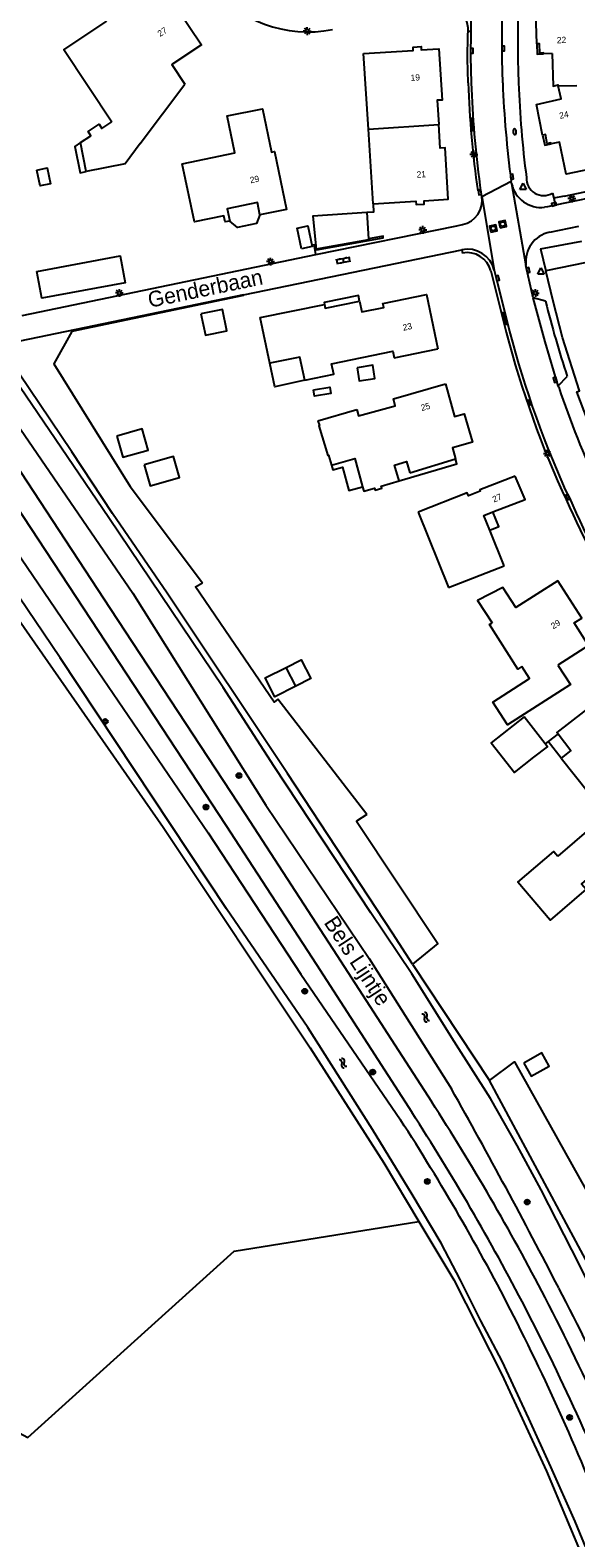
# Model space of a CAD drawing. Extents: x 126000 to 131009, y 393000 to 395500.
# Drawn here: x 130307.9 to 130394.9, y 394768.1 to 395008.4 of the extents above; entities that cross this region are included whole.
import ezdxf

# ---------------------------------------------------------------- set-up
doc = ezdxf.new("R2010")
doc.units = 0
for name, color, linetype in [('gg-afsc-erfafscheiding', 7, 'Continuous'), ('gg-afsc-hekwerk', 7, 'Continuous'), ('gg-afsc-muur', 7, 'Continuous'), ('gg-anno-huisnummerreeks BGT', 7, 'Continuous'), ('gg-anno-openbare ruimte label', 7, 'Continuous'), ('gg-bbg-bijgebouw', 7, 'Continuous'), ('gg-bbg-gedigitaliseerde bebouwing', 7, 'Continuous'), ('gg-bbg-gedigitaliseerde bijgebouw', 7, 'Continuous'), ('gg-bbg-hoofdgebouw', 7, 'Continuous'), ('gg-bbg-luifel en loopbrug', 7, 'Continuous'), ('gg-bbg-tussenscheiding', 7, 'Continuous'), ('gg-knt-verharding', 7, 'Continuous'), ('gg-knt-verharding nz', 7, 'Continuous'), ('gg-kntw-bovenkant insteek waterloop', 7, 'Continuous'), ('gt-grn-groengrens', 7, 'Continuous'), ('gt-grn-vlakafsluiter', 7, 'Continuous'), ('gt-grn-weggrens', 7, 'Continuous'), ('gt-symb-boom', 7, 'Continuous'), ('gt-symb-brandkraan', 7, 'Continuous'), ('gt-symb-klinker verharding', 7, 'Continuous'), ('gt-symb-kolk', 7, 'Continuous'), ('gt-symb-lichtmast', 7, 'Continuous'), ('gt-symb-rioolschacht', 7, 'Continuous'), ('gt-symb-tegel verharding', 7, 'Continuous'), ('gt-symb-waterafsluiter', 7, 'Continuous'), ('gt-symb-watersymbool', 7, 'Continuous')]:
    doc.layers.add(name, color=color, linetype=linetype)

# ---------------------------------------------------------------- blocks, each defined once
blk = doc.blocks.new('gt0-KOLK')
at = {"layer": 'gt-symb-kolk'}
blk.add_lwpolyline([(0, 0), (0.38, 0), (0.38, 0.4), (-0.37, 0.4), (-0.37, 0), (0, 0)], dxfattribs=at)
blk = doc.blocks.new('gt0-LMAST')
at = {"layer": 'gt-symb-lichtmast'}
for p, q in [((-0.18, 0.17), (-0.45, 0.44)), ((0, 0.25), (0, 0.62)), ((0.17, 0.17), (0.44, 0.44)), ((-0.25, 0), (-0.63, 0)), ((-0.18, -0.18), (-0.45, -0.45)), ((0, -0.25), (0, -0.63)), ((0.44, -0.45), (0.17, -0.18)), ((0.25, 0), (0.62, 0))]:
    blk.add_line(p, q, dxfattribs=at)
blk.add_circle((0, 0), 0.25, dxfattribs=at)
blk = doc.blocks.new('gt0-BR')
at = {"layer": 'gt-symb-brandkraan'}
for centre, radius, start, end in [((-0.24, 0), 0.206, 107.5669, 252.4331), ((0.6, -2.66), 3, 106.892, 107.5669), ((0, -0.69), 0.938, 73.108, 106.892), ((-0.6, -2.66), 3, 72.4331, 73.108), ((0.24, 0), 0.206, 287.567, 72.4331), ((0.6, 2.66), 3, 252.4331, 253.108), ((0, 0.69), 0.938, 253.108, 286.8921), ((-0.6, 2.66), 3, 286.8921, 287.567)]:
    blk.add_arc(centre, radius, start, end, dxfattribs=at)
blk = doc.blocks.new('gt0-WAFSL')
at = {"layer": 'gt-symb-waterafsluiter'}
for p, q in [((-0.5, -0.33), (0, 0.67)), ((0, 0.67), (0.5, -0.33)), ((0.5, -0.33), (-0.5, -0.33))]:
    blk.add_line(p, q, dxfattribs=at)
blk = doc.blocks.new('gt0-TEG1')
at = {"layer": 'gt-symb-tegel verharding'}
for p, q in [((-1.12, 0), (1.12, 0)), ((-0.9, -0.25), (-0.9, 0.25)), ((-0.45, -0.25), (-0.45, 0.25)), ((0, -0.25), (0, 0.25)), ((0.45, -0.25), (0.45, 0.25)), ((0.9, -0.25), (0.9, 0.25))]:
    blk.add_line(p, q, dxfattribs=at)
blk = doc.blocks.new('gt0-RS')
at = {"layer": 'gt-symb-rioolschacht'}
blk.add_lwpolyline([(-0.5, -0.5), (0.5, -0.5), (0.5, 0.5), (-0.5, 0.5)], close=True, dxfattribs=at)
blk.add_circle((0, 0), 0.375, dxfattribs=at)
blk = doc.blocks.new('gt0-BOOM')
at = {"layer": 'gt-symb-boom'}
for radius in [0.4, 0.2]:
    blk.add_circle((0, 0), radius, dxfattribs=at)
blk = doc.blocks.new('gt0-WA')
at = {"layer": 'gt-symb-watersymbool'}
for centre, start, end in [((-0.32, 0.02), 28.0725, 151.9275), ((0.43, 0.42), 208.0725, 331.9275), ((-0.32, -0.43), 28.0725, 151.9275), ((0.43, -0.03), 208.0725, 331.9275)]:
    blk.add_arc(centre, 0.425, start, end, dxfattribs=at)
blk = doc.blocks.new('gt0-KL1')
at = {"layer": 'gt-symb-klinker verharding'}
for p, q in [((-1.15, 0.3), (1.15, 0.3)), ((-1, -0.3), (-1, 0.3)), ((-0.5, 0.3), (-0.5, 0.45)), ((0, -0.3), (0, 0.3)), ((0.5, 0.3), (0.5, 0.45)), ((1, -0.3), (1, 0.3)), ((-1.15, -0.3), (1.15, -0.3)), ((-0.5, -0.45), (-0.5, -0.3)), ((0.5, -0.45), (0.5, -0.3))]:
    blk.add_line(p, q, dxfattribs=at)

msp = doc.modelspace()

# ---------------------------------------------------------------- linework, layer by layer
at = {"layer": 'gg-afsc-erfafscheiding'}
for p, q in [((130353.44, 394972.64), (130353.16, 394974.31)), ((130306.66, 394962.91), (130353.44, 394972.64))]:
    msp.add_line(p, q, dxfattribs=at)
for points in [[(130362.57, 394980.73), (130362.65, 394979.38), (130361.56, 394979.31)], [(130341.94, 394966.09), (130314.56, 394960.37), (130311.72, 394955.21), (130323.87, 394935.67), (130335.39, 394920.32)]]:
    msp.add_lwpolyline(points, dxfattribs=at)
at = {"layer": 'gg-afsc-hekwerk'}
msp.add_line((130368.85, 394859.54), (130381.11, 394841.01), dxfattribs=at)
for points in [[(130347.4, 394901.79), (130346.82, 394901.29), (130334.27, 394919.66), (130335.39, 394920.32)], [(130361.56, 394883.4), (130359.89, 394882.32), (130372.89, 394862.84), (130368.85, 394859.54)], [(130381.11, 394841.01), (130385.07, 394843.99), (130396.51, 394823.51), (130409.61, 394799.92)]]:
    msp.add_lwpolyline(points, dxfattribs=at)
at = {"layer": 'gg-afsc-muur'}
msp.add_line((130390.43, 394895.01), (130389.96, 394894.65), dxfattribs=at)
msp.add_lwpolyline([(130353.5, 394973.48), (130353.52, 394973.36), (130364.18, 394975.31), (130364.14, 394975.55), (130361.84, 394975.12)], dxfattribs=at)
at = {"layer": 'gg-bbg-bijgebouw'}
for p, q in [((130361.56, 394979.31), (130361.84, 394975.12)), ((130353.5, 394973.48), (130353.47, 394973.47)), ((130389.96, 394894.65), (130386.6, 394898.95))]:
    msp.add_line(p, q, dxfattribs=at)
msp.add_lwpolyline([(130361.84, 394975.12), (130361.84, 394974.99), (130353.5, 394973.48)], dxfattribs=at)
at = {"layer": 'gg-bbg-gedigitaliseerde bebouwing'}
for p, q in [((130361.81, 394992.62), (130361.04, 395004.65)), ((130325.47, 394990.31), (130332.59, 394999.8)), ((130362.57, 394980.73), (130361.81, 394992.62)), ((130316.87, 394985.88), (130315.94, 394990.47)), ((130346.13, 394955.3), (130344.56, 394962.59)), ((130365.9, 394956.16), (130372.87, 394957.6)), ((130353.78, 394946.14), (130359.96, 394947.94)), ((130368.42, 394937.87), (130375.69, 394940.07)), ((130369.72, 394931.6), (130374.55, 394919.56)), ((130374.55, 394919.56), (130383.44, 394923.02)), ((130403.79, 394886.91), (130391.98, 394876.78))]:
    msp.add_line(p, q, dxfattribs=at)
for points in [[(130320.09, 395009.83), (130313.3, 395005.33), (130320.95, 394993.8)], [(130315.94, 394990.47), (130317.61, 394991.58), (130317.17, 394992.24), (130318.92, 394993.41), (130319.36, 394992.74), (130320.95, 394993.8)], [(130325.47, 394990.31), (130323.07, 394987.11), (130316.87, 394985.88)], [(130351.68, 394952.59), (130356.28, 394953.55), (130355.93, 394955.21), (130365.68, 394957.24), (130365.9, 394956.16)], [(130351.68, 394952.59), (130350.91, 394956.3), (130346.13, 394955.3)], [(130359.96, 394947.94), (130360.25, 394946.92), (130366.09, 394948.55), (130365.79, 394949.64), (130374.07, 394952.05)], [(130353.78, 394946.14), (130354.02, 394945.37), (130353.91, 394945.34), (130355.36, 394940.61), (130355.47, 394940.64), (130355.94, 394939.09)], [(130355.94, 394939.09), (130359.63, 394940.12), (130360.89, 394935.63)], [(130366.71, 394936.56), (130365.97, 394939.07), (130367.9, 394939.64), (130368.42, 394937.87)], [(130360.89, 394935.63), (130361.09, 394934.91), (130362.8, 394935.41), (130362.89, 394935.09), (130363.97, 394935.41), (130363.87, 394935.72), (130366.71, 394936.56)], [(130392, 394920.63), (130385.32, 394916.36), (130383.25, 394919.57), (130379.2, 394917.52), (130381.51, 394913.92)], [(130386.27, 394906.97), (130385.62, 394906.55), (130381.08, 394913.65), (130381.51, 394913.92)], [(130392.01, 394907.21), (130394, 394904.1), (130383.97, 394897.69), (130381.65, 394901.32), (130387.5, 394905.05), (130386.27, 394906.97)], [(130392.02, 394896.24), (130394.05, 394893.61), (130392.51, 394892.39)], [(130392.51, 394892.39), (130396.85, 394886.92), (130408.44, 394896.11)], [(130399.53, 394875.58), (130395.78, 394872.33), (130396.49, 394871.5), (130390.75, 394866.58), (130385.6, 394872.6), (130391.34, 394877.51), (130391.98, 394876.78)]]:
    msp.add_lwpolyline(points, dxfattribs=at)
at = {"layer": 'gg-bbg-gedigitaliseerde bijgebouw'}
msp.add_line((130350.24, 394903.86), (130348.73, 394906.85), dxfattribs=at)
for points in [[(130309, 394986.09), (130310.64, 394986.43), (130311.17, 394983.93), (130309.53, 394983.58), (130309, 394986.09)], [(130361.56, 394979.31), (130352.96, 394978.74), (130353.47, 394973.47)], [(130308.97, 394969.95), (130322.28, 394972.44), (130323.08, 394968.15), (130309.77, 394965.66), (130308.97, 394969.95)], [(130360.03, 394954.59), (130360.36, 394952.49), (130362.85, 394952.88), (130362.52, 394954.98), (130360.03, 394954.59)], [(130321.71, 394943.68), (130322.67, 394940.32), (130326.71, 394941.48), (130325.75, 394944.84), (130321.71, 394943.68)], [(130326.09, 394939.11), (130327.05, 394935.78), (130331.72, 394937.11), (130330.76, 394940.45), (130326.09, 394939.11)], [(130348.73, 394906.85), (130351.12, 394908.05), (130352.62, 394905.06), (130350.24, 394903.86)], [(130386.6, 394898.95), (130381.38, 394894.84), (130385.07, 394890.11), (130388.19, 394892.54)], [(130386.57, 394843.79), (130387.74, 394841.69), (130390.62, 394843.3), (130389.45, 394845.4), (130386.57, 394843.79)]]:
    msp.add_lwpolyline(points, dxfattribs=at)
at = {"layer": 'gg-bbg-hoofdgebouw'}
for p, q in [((130391.06, 395004.65), (130389.73, 395004.6)), ((130344.56, 394962.59), (130354.81, 394964.7)), ((130383.44, 394923.02), (130381.15, 394928.72)), ((130396.9, 394910.33), (130392.01, 394907.21))]:
    msp.add_line(p, q, dxfattribs=at)
for points in [[(130329.45, 395014.7), (130335.2, 395006.05), (130330.51, 395002.93), (130332.59, 394999.8)], [(130388.63, 395006.22), (130388.46, 395011.18), (130392, 395011.31), (130391.9, 395014.36)], [(130361.04, 395004.65), (130368.94, 395005.15), (130368.92, 395005.7), (130370.22, 395005.81), (130370.24, 395005.25), (130373.04, 395005.42), (130373.54, 394997.25), (130372.78, 394997.23), (130373.01, 394993.34)], [(130389.73, 395004.6), (130389.72, 395004.76), (130389.11, 395004.74), (130389.06, 395006.24), (130388.63, 395006.22)], [(130391.06, 395004.65), (130391.25, 394999.49), (130392.01, 394999.66), (130392.04, 394999.51)], [(130389.57, 394991.67), (130388.57, 394996.53), (130392.52, 394997.45), (130392.04, 394999.51)], [(130332.15, 394987.09), (130340.52, 394988.87), (130339.31, 394994.73), (130344.94, 394995.88), (130346.36, 394988.97), (130346.87, 394989.08), (130348.76, 394979.83), (130344.53, 394978.96)], [(130362.57, 394980.73), (130369.37, 394981.14), (130369.4, 394980.59), (130370.72, 394980.67), (130370.69, 394981.22), (130374.51, 394981.46), (130374.02, 394989.62), (130373.25, 394989.57), (130373.01, 394993.34)], [(130390.92, 394990.27), (130390.89, 394990.42), (130390.3, 394990.3), (130390, 394991.76), (130389.57, 394991.67)], [(130401.22, 394987.09), (130393.32, 394985.45), (130392.24, 394990.55), (130390.92, 394990.27)], [(130339.73, 394977.98), (130338.99, 394977.83), (130338.8, 394978.78), (130334.12, 394977.83), (130332.15, 394987.09)], [(130344.53, 394978.96), (130344.13, 394980.92), (130339.32, 394979.94), (130339.73, 394977.98)], [(130360.4, 394965.2), (130360.75, 394963.49), (130364.25, 394964.19), (130364.12, 394964.83), (130371.06, 394966.26), (130372.87, 394957.6)], [(130354.81, 394964.7), (130354.93, 394964.07), (130360.4, 394965.2)], [(130374.07, 394952.05), (130375.53, 394946.82), (130377.09, 394947.25), (130378.39, 394942.75), (130375.19, 394941.85), (130375.69, 394940.07)], [(130385.21, 394937.33), (130379.56, 394935.13), (130379.64, 394934.93), (130377.76, 394934.16), (130377.56, 394934.65), (130369.72, 394931.6)], [(130381.64, 394931.61), (130386.79, 394933.59), (130385.21, 394937.33)], [(130381.15, 394928.72), (130380.21, 394931.06), (130381.64, 394931.61)], [(130396.9, 394910.33), (130394.61, 394913.92), (130395.79, 394914.68), (130392, 394920.63)], [(130401.98, 394904.32), (130391.83, 394896.47), (130392.02, 394896.24)]]:
    msp.add_lwpolyline(points, dxfattribs=at)
at = {"layer": 'gg-bbg-luifel en loopbrug'}
for p in [(130392.02, 394896.24), (130392.51, 394892.39)]:
    msp.add_line(p, (130390.43, 394895.01), dxfattribs=at)
for points in [[(130388.63, 395006.22), (130388.69, 395004.56), (130389.73, 395004.6)], [(130315.94, 394990.47), (130315.05, 394989.88), (130315.9, 394985.68), (130316.87, 394985.88)], [(130389.57, 394991.67), (130389.9, 394990.06), (130390.92, 394990.27)], [(130344.53, 394978.96), (130343.96, 394977.59), (130340.97, 394976.97), (130339.73, 394977.98)], [(130351.13, 394973.57), (130350.46, 394976.85), (130352.17, 394977.2), (130352.84, 394973.92), (130351.13, 394973.57)], [(130335.13, 394963.18), (130335.84, 394959.76), (130339.25, 394960.47), (130338.55, 394963.88), (130335.13, 394963.18)], [(130360.4, 394965.2), (130360.22, 394966.1), (130354.75, 394965), (130354.81, 394964.7)], [(130351.68, 394952.59), (130346.93, 394951.57), (130346.13, 394955.3)], [(130353.04, 394951.1), (130355.66, 394951.51), (130355.82, 394950.49), (130353.2, 394950.08), (130353.04, 394951.1)], [(130366.71, 394936.56), (130375.92, 394939.28), (130375.69, 394940.07)], [(130355.94, 394939.09), (130356.15, 394938.32), (130357.67, 394938.75), (130358.71, 394935.02), (130360.89, 394935.63)], [(130381.15, 394928.72), (130382.57, 394929.29), (130381.64, 394931.61)], [(130350.24, 394903.86), (130346.88, 394902.17), (130345.37, 394905.16), (130348.73, 394906.85)]]:
    msp.add_lwpolyline(points, dxfattribs=at)
at = {"layer": 'gg-bbg-tussenscheiding'}
for p, q in [((130392.04, 394999.51), (130395.04, 394999.6)), ((130361.81, 394992.62), (130373.01, 394993.34))]:
    msp.add_line(p, q, dxfattribs=at)
msp.add_lwpolyline([(130388.19, 394892.54), (130390.32, 394894.18), (130389.96, 394894.65)], dxfattribs=at)
at = {"layer": 'gg-knt-verharding'}
for p, q in [((130377.68, 395008.25), (130378.13, 395008.24)), ((130415.63, 394985.47), (130391.56, 394980.49)), ((130392.98, 394981.95), (130415.38, 394986.63)), ((130379.71, 394982.84), (130379.59, 394983.71)), ((130384.62, 394983.96), (130384.56, 394984.31)), ((130379.24, 394982.77), (130379.71, 394982.84)), ((130391.13, 394982.43), (130391.33, 394981.62)), ((130392.98, 394981.95), (130391.33, 394981.62)), ((130353.44, 394972.64), (130375.91, 394977.23)), ((130375.91, 394977.23), (130376.81, 394977.42)), ((130390.71, 394976.21), (130395.32, 394977.18)), ((130341.92, 394966.2), (130376.7, 394973.4)), ((130376.7, 394973.4), (130376.81, 394972.86)), ((130389.24, 394973.52), (130395.82, 394974.79)), ((130389.24, 394973.52), (130390.07, 394970.04)), ((130381.32, 394970.02), (130383.33, 394961.99)), ((130381.86, 394970.16), (130382.07, 394969.29)), ((130382.07, 394969.29), (130383.86, 394962.12)), ((130390.04, 394965.18), (130388.06, 394965.71)), ((130392.06, 394951.73), (130393.5, 394953.19)), ((130392.13, 394951.48), (130392.06, 394951.73)), ((130392.68, 394934.92), (130393.33, 394933.61)), ((130393.18, 394935.14), (130393.83, 394933.84))]:
    msp.add_line(p, q, dxfattribs=at)
for points in [[(130377.71, 395000), (130377.62, 395003.83), (130377.64, 395007.67), (130377.68, 395008.25)], [(130378.13, 395008.24), (130378.1, 395004.12), (130378.19, 395000)], [(130379.88, 394981.9), (130379.88, 394981.9), (130379.71, 394982.84)], [(130391.56, 394980.49), (130390.33, 394980.23), (130389.88, 394980.16)], [(130388.06, 394965.71), (130386.99, 394970.41), (130386.9, 394970.88)], [(130400.84, 394936.26), (130397.78, 394943.46), (130395.02, 394950.78), (130395.42, 394950.91), (130392.75, 394959.41), (130391.22, 394965.21), (130390.07, 394970.04)], [(130341.92, 394966.2), (130303.2, 394958.17), (130303.05, 394958.86)], [(130291.2, 394954.58), (130317.59, 394914.47), (130339.1, 394881.69), (130353.55, 394859.51), (130368.71, 394835.95)], [(130295.17, 394955.17), (130296.17, 394953.51), (130320.69, 394916.21), (130342.22, 394883.38), (130356.8, 394860.99), (130371.86, 394837.65)]]:
    msp.add_lwpolyline(points, dxfattribs=at)
for centre, radius, start, end in [((130550.55, 395006.52), 167.48, 172.0808, 182.2328), ((130551.86, 395006.24), 166.26, 172.0045, 182.1512), ((130553.09, 395006.39), 174.98, 175.227, 179.394), ((130352.24, 395028.4), 20.29, 218.6521, 280.986), ((130374.38, 395008.58), 3.32, 354.283, 65.702), ((130534.6, 395005.27), 156.98, 181.9255, 188.2426), ((130535.08, 395005.26), 156.98, 181.9205, 187.8903), ((130550.59, 395006.53), 167.51, 182.2348, 187.6231), ((130551.46, 395006.22), 165.85, 182.1485, 187.3845), ((130389.35, 394984.97), 4.83, 192.0154, 276.3674), ((130389.72, 394984.78), 2.74, 177.4339, 301.0781), ((130376.02, 394981.25), 3.91, 281.7077, 9.5719), ((130391.71, 394971.48), 4.84, 101.8542, 187.044), ((130377.59, 394969.09), 4.4, 13.9987, 101.6735), ((130377.59, 394969.09), 3.85, 14.0059, 101.6734), ((130536.26, 395000.93), 150.53, 193.7386, 198.4914), ((130540.78, 395001.24), 162.28, 193.9971, 204.1228), ((130540.72, 395001.21), 161.66, 193.9946, 204.1245), ((130537.73, 395000.2), 153.53, 198.5028, 204.9395), ((130541.7, 394998.6), 161.99, 203.6527, 218.7213), ((130541.76, 394998.64), 161.5, 203.6556, 218.7189), ((130049.56, 394629.92), 383.44, 27.4096, 32.8034), ((130052.31, 394631.55), 376.69, 27.3753, 32.8629), ((130049.54, 394629.94), 383.45, 20.978, 27.4057), ((130052.12, 394631.42), 376.92, 21.3087, 27.3799)]:
    msp.add_arc(centre, radius, start, end, dxfattribs=at)
at = {"layer": 'gg-knt-verharding nz'}
msp.add_lwpolyline([(130392.06, 394951.73), (130389.97, 394958.7), (130388.06, 394965.71)], dxfattribs=at)
at = {"layer": 'gg-kntw-bovenkant insteek waterloop'}
for points in [[(130414.31, 394771.26), (130410.08, 394780.34), (130406.92, 394787.68), (130400.34, 394801.91), (130394.22, 394814), (130389.33, 394823.58), (130385.5, 394830.66), (130381.27, 394838.14), (130375.45, 394847.24), (130368.73, 394858.02), (130362.18, 394867.72), (130346.79, 394891.05), (130338.65, 394903.66), (130320.47, 394930.69), (130305.36, 394952.89), (130303.67, 394955.23), (130301.53, 394954.42), (130301.07, 394954)], [(130301.07, 394954), (130301.04, 394952.55), (130324.28, 394918.68), (130345.47, 394884.9), (130361.93, 394860.45), (130375.04, 394839.66)], [(130284.95, 394950.01), (130286.14, 394950.89), (130288, 394951.36), (130314.8, 394912.03), (130336.26, 394880.49), (130351.07, 394857.95), (130366.91, 394834.75)], [(130427.63, 394665.15), (130426.05, 394670.47), (130423.14, 394683.22), (130419.53, 394697.87), (130416.49, 394708.15), (130413.34, 394719.45), (130410.33, 394729.27), (130407.67, 394737.45), (130404.96, 394745.02), (130401.89, 394752.73), (130398.65, 394761.31), (130394.73, 394770.7), (130390.87, 394779.42), (130387.39, 394787.13), (130383.11, 394796.26), (130379.7, 394802.73), (130376.5, 394809.2), (130373.41, 394815.06), (130368.8, 394822.84), (130362.49, 394833.17), (130352.17, 394849.44), (130339.18, 394868.34), (130312.69, 394908.34), (130298.27, 394929.68)]]:
    msp.add_lwpolyline(points, dxfattribs=at)
for centre, radius, start, end in [((129502.61, 394349.03), 1000.93, 27.28926, 29.35231), ((130074.2, 394644.95), 348.86, 27.0238, 32.9608), ((129502.49, 394348.89), 1001.1, 24.95233, 27.29306), ((130074.16, 394644.95), 348.89, 20.2997, 27.0208)]:
    msp.add_arc(centre, radius, start, end, dxfattribs=at)
at = {"layer": 'gt-grn-groengrens'}
for p, q in [((130396.54, 394971.38), (130390.07, 394970.04)), ((130361.56, 394883.4), (130347.4, 394901.79))]:
    msp.add_line(p, q, dxfattribs=at)
for points in [[(130368.85, 394859.54), (130365.67, 394864.51), (130358.01, 394876.13), (130348.95, 394889.93), (130329.76, 394918.66), (130321.07, 394931.37), (130314.55, 394941.18), (130302.65, 394958.78)], [(130282.69, 394947.97), (130329.1, 394881.36), (130352.55, 394846.19), (130364.27, 394827.87), (130369.85, 394818.55)], [(130405.52, 394794.77), (130401.74, 394802.56), (130381.11, 394841.01)], [(130236.28, 394788.4), (130281.06, 394798.36), (130307.57, 394784.11), (130340.41, 394813.8), (130369.85, 394818.55)], [(130369.85, 394818.55), (130375.42, 394809.23), (130383.08, 394794.16), (130390.16, 394778.77), (130405.31, 394742.62), (130417.03, 394703.05), (130424.16, 394671.74), (130425.35, 394665.9)]]:
    msp.add_lwpolyline(points, dxfattribs=at)
at = {"layer": 'gt-grn-vlakafsluiter'}
msp.add_line((130341.94, 394966.09), (130341.92, 394966.2), dxfattribs=at)
at = {"layer": 'gt-grn-weggrens'}
for p, q in [((130379.88, 394981.9), (130384.56, 394984.31)), ((130384.62, 394983.96), (130386.9, 394970.88)), ((130379.88, 394981.9), (130381.86, 394970.16)), ((130391.33, 394981.62), (130391.56, 394980.49))]:
    msp.add_line(p, q, dxfattribs=at)

# ---------------------------------------------------------------- block references
at = {"layer": 'gt-symb-boom'}
for p in [(130319.88, 394898.22), (130341.19, 394889.6), (130335.94, 394884.58), (130351.68, 394855.22), (130362.5, 394842.35), (130371.2, 394824.93), (130387.11, 394821.63), (130393.86, 394787.32)]:
    msp.add_blockref('gt0-BOOM', p, dxfattribs=at)
at = {"layer": 'gt-symb-brandkraan', "rotation": 94.75888567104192}
msp.add_blockref('gt0-BR', (130385.12, 394992.2), dxfattribs=at)
at = {"layer": 'gt-symb-klinker verharding', "rotation": 11.7145252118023}
msp.add_blockref('gt0-KL1', (130357.83, 394971.71), dxfattribs=at)
at = {"layer": 'gt-symb-kolk'}
for p, rotation in [((130378.1, 395005.1), -90.1145914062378), ((130383.08, 395005.46), -89.59893609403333), ((130384.47, 394985), -82.53402593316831), ((130379.76, 394982.58), 99.66950525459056), ((130391.42, 394980.46), 15.00891367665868), ((130382.19, 394968.82), -75.88039706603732), ((130387.05, 394970.11), -77.22875743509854), ((130391.76, 394952.72), 106.67729393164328), ((130387.69, 394949.12), 108.90606099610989), ((130393.72, 394934.04), 115.20722121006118)]:
    msp.add_blockref('gt0-KOLK', p, dxfattribs=dict(at, rotation=rotation))
at = {"layer": 'gt-symb-lichtmast'}
for p in [(130352.07, 395008.25), (130378.61, 394988.58), (130394.22, 394981.58), (130370.48, 394976.57), (130346.22, 394971.51), (130322.14, 394966.51), (130388.42, 394966.5), (130390.31, 394940.89)]:
    msp.add_blockref('gt0-LMAST', p, dxfattribs=at)
at = {"layer": 'gt-symb-rioolschacht', "rotation": 11.366137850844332}
for p in [(130381.71, 394976.79), (130383.2, 394977.48)]:
    msp.add_blockref('gt0-RS', p, dxfattribs=at)
at = {"layer": 'gt-symb-tegel verharding'}
for p, rotation in [((130378.3, 394993.37), 96.25793391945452), ((130383.51, 394962.48), -75.9915565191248)]:
    msp.add_blockref('gt0-TEG1', p, dxfattribs=dict(at, rotation=rotation))
at = {"layer": 'gt-symb-waterafsluiter'}
for p in [(130386.46, 394983.35), (130389.3, 394969.83)]:
    msp.add_blockref('gt0-WAFSL', p, dxfattribs=at)
at = {"layer": 'gt-symb-watersymbool'}
for p, rotation in [((130370.92, 394851.13), -57.040990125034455), ((130357.73, 394843.82), -57.04099012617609)]:
    msp.add_blockref('gt0-WA', p, dxfattribs=dict(at, rotation=rotation))

# ---------------------------------------------------------------- texts
at = {"layer": 'gg-anno-huisnummerreeks BGT'}
for s, rotation, p in [('27', 33.6, (130328.63, 395007.29)), ('22', 1.9, (130391.85, 395006.3)), ('19', 3.6, (130368.57, 395000.3)), ('24', 11.7, (130392.33, 394994.25)), ('21', 3.4, (130369.52, 394984.87)), ('29', 11.5, (130343.04, 394983.97)), ('23', 11.8, (130367.39, 394960.48)), ('25', 15.6, (130370.32, 394947.69)), ('27', 22.9, (130381.81, 394933.09)), ('29', 32.5, (130391.27, 394912.89))]:
    msp.add_text(s, height=1, rotation=rotation, dxfattribs=at).set_placement(p)
at = {"layer": 'gg-anno-openbare ruimte label'}
for s, rotation, p in [('Genderbaan', 11.7, (130326.97, 394964.14)), ('Bels Lijntje', 303.2, (130354.64, 394866.16))]:
    msp.add_text(s, height=2.5, rotation=rotation, dxfattribs=at).set_placement(p)

doc.saveas('drawing.dxf')
